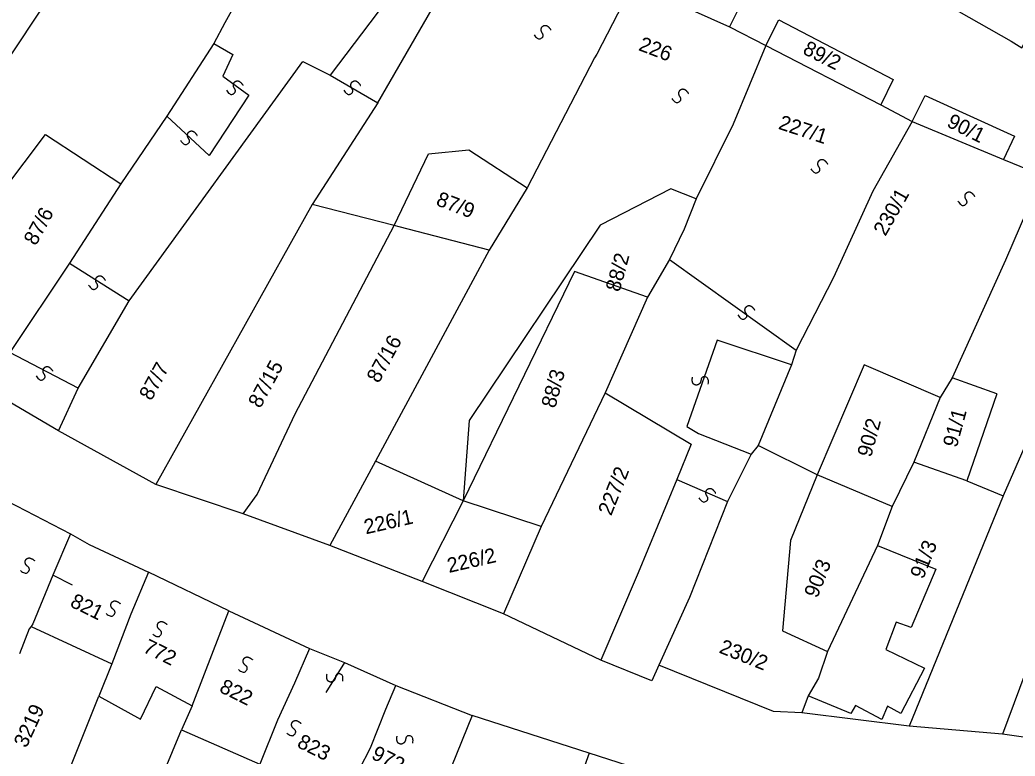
# Model space of a CAD drawing. Extents: x -581999 to -572728, y -1219553 to -1212032.
# Drawn here: x -578208.2 to -578073.6, y -1215897.1 to -1215797.5 of the extents above; entities that cross this region are included whole.
import ezdxf

# ---------------------------------------------------------------- set-up
doc = ezdxf.new("R2010")
doc.units = 0
for name, color, linetype in [('Vrstva 1', 7, 'Continuous'), ('Vrstva 2', 7, 'Continuous'), ('Vrstva 4', 7, 'Continuous'), ('Vrstva 6', 7, 'Continuous')]:
    doc.layers.add(name, color=color, linetype=linetype)

msp = doc.modelspace()

# ---------------------------------------------------------------- linework, layer by layer
at = {"layer": 'Vrstva 1'}
for p, q in [((-578133.148, -1215831.536), (-578148.235, -1215862.576)), ((-578123.291, -1215835.015), (-578133.148, -1215831.536)), ((-578119.321, -1215859.694), (-578124.539, -1215872.309)), ((-578080.096, -1215859.877), (-578075.208, -1215861.874)), ((-578148.235, -1215862.576), (-578153.775, -1215873.463))]:
    msp.add_line(p, q, dxfattribs=at)
for points in [[(-578170.788, -1215780.545), (-578180.468, -1215797.94)], [(-578231.766, -1215836.027), (-578201.443, -1215790.286)], [(-578155.491, -1215790.809), (-578166.223, -1215805.007)], [(-578159.75, -1215808.746), (-578150.734, -1215793.081)], [(-578125.238, -1215792.614), (-578130.145, -1215802.172), (-578130.44, -1215802.654)], [(-578125.238, -1215792.614), (-578112.187, -1215798.456)], [(-578084.212, -1215794.651), (-578074.129, -1215800.41)], [(-578180.468, -1215797.94), (-578181.927, -1215800.729)], [(-578112.187, -1215798.456), (-578107.285, -1215800.983)], [(-578107.285, -1215800.983), (-578105.521, -1215797.542), (-578090.077, -1215805.59), (-578091.75, -1215809.03)], [(-578181.927, -1215800.729), (-578188.289, -1215810.551)], [(-578107.285, -1215800.983), (-578111.689, -1215811.643)], [(-578107.285, -1215800.983), (-578091.75, -1215809.03)], [(-578074.129, -1215800.41), (-578072.652, -1215801.296), (-578072.037, -1215800.152)], [(-578130.44, -1215802.654), (-578139.56, -1215820.226)], [(-578193.376, -1215835.515), (-578169.922, -1215803.135), (-578166.223, -1215805.007)], [(-578087.497, -1215811.275), (-578085.731, -1215807.742), (-578073.664, -1215813.244), (-578075.152, -1215816.405)], [(-578159.75, -1215808.746), (-578168.628, -1215822.506)], [(-578091.75, -1215809.03), (-578087.497, -1215811.275)], [(-578188.289, -1215810.551), (-578194.518, -1215819.709)], [(-578111.689, -1215811.643), (-578116.729, -1215821.731)], [(-578087.497, -1215811.275), (-578092.824, -1215820.696)], [(-578087.497, -1215811.275), (-578075.152, -1215816.405)], [(-578225.23, -1215840.186), (-578204.682, -1215813.018), (-578194.518, -1215819.709)], [(-578157.527, -1215825.326), (-578152.885, -1215815.634), (-578147.463, -1215815.116), (-578139.56, -1215820.226)], [(-578075.152, -1215816.405), (-578071.73, -1215817.81)], [(-578070.039, -1215818.857), (-578074.879, -1215830.017), (-578082.113, -1215845.93)], [(-578194.518, -1215819.709), (-578201.475, -1215830.426)], [(-578139.56, -1215820.226), (-578144.709, -1215828.681)], [(-578116.729, -1215821.731), (-578120.146, -1215820.387), (-578129.671, -1215825.28), (-578147.425, -1215851.682), (-578148.235, -1215862.576)], [(-578092.824, -1215820.696), (-578098.132, -1215832.377)], [(-578168.628, -1215822.506), (-578189.798, -1215860.374)], [(-578157.527, -1215825.326), (-578168.628, -1215822.506)], [(-578116.729, -1215821.731), (-578118.322, -1215825.846)], [(-578176.09, -1215861.696), (-578170.918, -1215850.812), (-578157.527, -1215825.326)], [(-578156.88, -1215825.496), (-578157.527, -1215825.326)], [(-578144.709, -1215828.681), (-578156.88, -1215825.496)], [(-578118.322, -1215825.846), (-578120.326, -1215829.93)], [(-578144.709, -1215828.681), (-578160.088, -1215857.216)], [(-578201.475, -1215830.426), (-578209.516, -1215842.511)], [(-578120.326, -1215829.93), (-578123.291, -1215835.015), (-578128.997, -1215847.974)], [(-578098.132, -1215832.377), (-578103.171, -1215842.196)], [(-578200.268, -1215847.328), (-578193.376, -1215835.515)], [(-578103.171, -1215842.196), (-578103.835, -1215844.188)], [(-578103.835, -1215844.188), (-578108.347, -1215855.071)], [(-578083.703, -1215848.582), (-578093.998, -1215844.174), (-578100.367, -1215859.037)], [(-578082.113, -1215845.93), (-578083.703, -1215848.582)], [(-578076.059, -1215848.085), (-578082.113, -1215845.93)], [(-578202.918, -1215853.089), (-578212.731, -1215847.387)], [(-578202.918, -1215853.089), (-578200.268, -1215847.328)], [(-578128.997, -1215847.974), (-578137.667, -1215866.016)], [(-578128.997, -1215847.974), (-578117.397, -1215854.916)], [(-578076.059, -1215848.085), (-578080.096, -1215859.877), (-578087.286, -1215857.341)], [(-578083.703, -1215848.582), (-578087.286, -1215857.341)], [(-578070.393, -1215850.865), (-578075.208, -1215861.874), (-578087.892, -1215893.03)], [(-578189.798, -1215860.374), (-578202.918, -1215853.089)], [(-578117.397, -1215854.916), (-578119.321, -1215859.694)], [(-578108.347, -1215855.071), (-578109.274, -1215856.264)], [(-578100.367, -1215859.037), (-578108.347, -1215855.071)], [(-578109.274, -1215856.264), (-578112.455, -1215862.633)], [(-578160.088, -1215857.216), (-578166.258, -1215868.595)], [(-578148.235, -1215862.576), (-578160.088, -1215857.216)], [(-578087.286, -1215857.341), (-578090.203, -1215863.312)], [(-578100.367, -1215859.037), (-578103.951, -1215867.929), (-578105.03, -1215880.146)], [(-578090.203, -1215863.312), (-578100.367, -1215859.037)], [(-578177.949, -1215864.311), (-578189.798, -1215860.374)], [(-578212.307, -1215861.346), (-578201.33, -1215867.035)], [(-578177.949, -1215864.311), (-578176.09, -1215861.696)], [(-578062.948, -1215860.927), (-578075.305, -1215894.097)], [(-578137.667, -1215866.016), (-578148.235, -1215862.576)], [(-578112.455, -1215862.633), (-578117.631, -1215875.639)], [(-578166.258, -1215868.595), (-578177.949, -1215864.311)], [(-578090.203, -1215863.312), (-578092.195, -1215868.62)], [(-578201.33, -1215867.035), (-578203.725, -1215872.596)], [(-578201.33, -1215867.035), (-578198.775, -1215868.468)], [(-578137.667, -1215866.016), (-578142.757, -1215877.861)], [(-578198.775, -1215868.468), (-578190.751, -1215872.223)], [(-578142.757, -1215877.861), (-578153.775, -1215873.463), (-578166.258, -1215868.595)], [(-578092.195, -1215868.62), (-578098.959, -1215882.948)], [(-578203.725, -1215872.596), (-578206.401, -1215879.215), (-578206.643, -1215879.549)], [(-578190.751, -1215872.223), (-578193.147, -1215877.88)], [(-578179.893, -1215877.421), (-578190.751, -1215872.223)], [(-578124.539, -1215872.309), (-578129.623, -1215884.124)], [(-578117.631, -1215875.639), (-578121.758, -1215884.793)], [(-578193.147, -1215877.88), (-578195.734, -1215884.593)], [(-578182.001, -1215882.791), (-578179.893, -1215877.421)], [(-578179.893, -1215877.421), (-578169.017, -1215882.531)], [(-578129.623, -1215884.124), (-578142.757, -1215877.861)], [(-578206.643, -1215879.549), (-578206.886, -1215879.884), (-578208.228, -1215883.24)], [(-578206.643, -1215879.549), (-578195.734, -1215884.593)], [(-578105.03, -1215880.146), (-578098.959, -1215882.948)], [(-578184.877, -1215890.269), (-578182.001, -1215882.791)], [(-578169.017, -1215882.531), (-578171.028, -1215887.229)], [(-578169.017, -1215882.531), (-578164.261, -1215884.44), (-578157.303, -1215887.545)], [(-578098.959, -1215882.948), (-578100.154, -1215886.532)], [(-578195.734, -1215884.593), (-578197.478, -1215888.994)], [(-578121.758, -1215884.793), (-578122.685, -1215886.893), (-578129.623, -1215884.124)], [(-578102.414, -1215891.231), (-578106.242, -1215891.051), (-578121.758, -1215884.793)], [(-578171.028, -1215887.229), (-578173.327, -1215892.214)], [(-578100.154, -1215886.532), (-578101.553, -1215888.916), (-578102.414, -1215891.231)], [(-578197.478, -1215888.994), (-578191.849, -1215892.077), (-578189.742, -1215887.668), (-578184.877, -1215890.269)], [(-578160.752, -1215895.963), (-578158.694, -1215890.757), (-578157.303, -1215887.545)], [(-578157.303, -1215887.545), (-578147.001, -1215891.58)], [(-578203.706, -1215904.526), (-578197.478, -1215888.994)], [(-578184.877, -1215890.269), (-578186.313, -1215893.529)], [(-578087.892, -1215893.03), (-578102.414, -1215891.231)], [(-578173.327, -1215892.214), (-578175.722, -1215898.158)], [(-578147.001, -1215891.58), (-578149.78, -1215898.481)], [(-578131.187, -1215896.691), (-578147.001, -1215891.58)], [(-578193.402, -1215910.593), (-578186.313, -1215893.529)], [(-578186.313, -1215893.529), (-578175.722, -1215898.158)], [(-578075.305, -1215894.097), (-578087.892, -1215893.03)], [(-578063.912, -1215895.722), (-578075.305, -1215894.097)], [(-578164.775, -1215905.26), (-578162.221, -1215898.842), (-578160.752, -1215895.963)], [(-578131.187, -1215896.691), (-578133.775, -1215903.976)], [(-578120.696, -1215900.07), (-578131.187, -1215896.691)]]:
    msp.add_lwpolyline(points, dxfattribs=at)
at = {"layer": 'Vrstva 4'}
for p, q in [((-578092.195, -1215868.62), (-578084.314, -1215871.789)), ((-578084.314, -1215871.789), (-578087.634, -1215879.694)), ((-578089.677, -1215878.975), (-578091.082, -1215882.688)), ((-578087.634, -1215879.694), (-578089.677, -1215878.975)), ((-578091.082, -1215882.688), (-578085.846, -1215885.203)), ((-578085.846, -1215885.203), (-578089.039, -1215891.312)), ((-578095.806, -1215891.312), (-578101.553, -1215888.916)), ((-578095.168, -1215890.234), (-578095.806, -1215891.312)), ((-578091.593, -1215892.15), (-578095.168, -1215890.234)), ((-578090.826, -1215890.353), (-578091.593, -1215892.15)), ((-578089.039, -1215891.312), (-578090.826, -1215890.353))]:
    msp.add_line(p, q, dxfattribs=at)
for points in [[(-578123.711, -1215789.132), (-578110.701, -1215795.48), (-578112.187, -1215798.456)], [(-578181.927, -1215800.729), (-578179.384, -1215802.195), (-578180.726, -1215805.127), (-578177.203, -1215807.704), (-578182.565, -1215815.884), (-578188.289, -1215810.551)], [(-578166.223, -1215805.007), (-578159.75, -1215808.746)], [(-578201.475, -1215830.426), (-578193.376, -1215835.515)], [(-578120.326, -1215829.93), (-578103.171, -1215842.196)], [(-578103.835, -1215844.188), (-578113.871, -1215840.842), (-578117.987, -1215852.523), (-578116.404, -1215853.457)], [(-578200.268, -1215847.328), (-578209.516, -1215842.511)], [(-578116.404, -1215853.457), (-578109.274, -1215856.264)], [(-578119.321, -1215859.694), (-578112.455, -1215862.633)], [(-578201.069, -1215873.973), (-578203.725, -1215872.596)], [(-578164.261, -1215884.44), (-578166.78, -1215888.483)]]:
    msp.add_lwpolyline(points, dxfattribs=at)
at = {"layer": 'Vrstva 6'}
for points in [[(-578138.625, -1215799.532), (-578138.145, -1215800.239), (-578137.451, -1215799.928), (-578137.374, -1215799.528), (-578137.61, -1215799.183), (-578137.695, -1215798.851), (-578137.613, -1215798.561), (-578137.469, -1215798.381), (-578137.233, -1215798.253), (-578136.868, -1215798.289), (-578136.441, -1215798.728), (-578136.386, -1215798.901)], [(-578180.243, -1215807.038), (-578179.763, -1215807.745), (-578179.069, -1215807.434), (-578178.992, -1215807.034), (-578179.228, -1215806.689), (-578179.313, -1215806.357), (-578179.231, -1215806.067), (-578179.087, -1215805.887), (-578178.851, -1215805.759), (-578178.486, -1215805.795), (-578178.059, -1215806.234), (-578178.004, -1215806.407)], [(-578164.363, -1215807.039), (-578163.883, -1215807.746), (-578163.189, -1215807.435), (-578163.112, -1215807.035), (-578163.348, -1215806.69), (-578163.433, -1215806.358), (-578163.351, -1215806.068), (-578163.207, -1215805.888), (-578162.971, -1215805.76), (-578162.606, -1215805.796), (-578162.179, -1215806.235), (-578162.124, -1215806.408)], [(-578120.006, -1215808.137), (-578119.526, -1215808.844), (-578118.832, -1215808.533), (-578118.755, -1215808.133), (-578118.991, -1215807.788), (-578119.076, -1215807.456), (-578118.994, -1215807.166), (-578118.85, -1215806.986), (-578118.614, -1215806.858), (-578118.249, -1215806.894), (-578117.822, -1215807.333), (-578117.767, -1215807.506)], [(-578186.449, -1215813.812), (-578185.969, -1215814.519), (-578185.275, -1215814.208), (-578185.198, -1215813.808), (-578185.434, -1215813.463), (-578185.519, -1215813.131), (-578185.437, -1215812.841), (-578185.293, -1215812.661), (-578185.057, -1215812.533), (-578184.692, -1215812.569), (-578184.265, -1215813.008), (-578184.21, -1215813.181)], [(-578101.204, -1215817.658), (-578100.724, -1215818.365), (-578100.03, -1215818.054), (-578099.953, -1215817.654), (-578100.189, -1215817.309), (-578100.274, -1215816.977), (-578100.192, -1215816.687), (-578100.048, -1215816.507), (-578099.812, -1215816.379), (-578099.447, -1215816.415), (-578099.02, -1215816.854), (-578098.965, -1215817.027)], [(-578081.307, -1215822.052), (-578080.827, -1215822.759), (-578080.133, -1215822.448), (-578080.056, -1215822.048), (-578080.292, -1215821.703), (-578080.377, -1215821.371), (-578080.295, -1215821.081), (-578080.151, -1215820.901), (-578079.915, -1215820.773), (-578079.55, -1215820.809), (-578079.123, -1215821.248), (-578079.068, -1215821.421)], [(-578198.862, -1215833.402), (-578198.382, -1215834.109), (-578197.688, -1215833.798), (-578197.611, -1215833.398), (-578197.847, -1215833.053), (-578197.932, -1215832.721), (-578197.85, -1215832.431), (-578197.706, -1215832.251), (-578197.47, -1215832.123), (-578197.105, -1215832.159), (-578196.678, -1215832.598), (-578196.623, -1215832.771)], [(-578111.061, -1215837.431), (-578110.581, -1215838.138), (-578109.887, -1215837.827), (-578109.81, -1215837.427), (-578110.046, -1215837.082), (-578110.131, -1215836.75), (-578110.049, -1215836.46), (-578109.905, -1215836.28), (-578109.669, -1215836.152), (-578109.304, -1215836.188), (-578108.877, -1215836.627), (-578108.822, -1215836.8)], [(-578205.981, -1215845.67), (-578205.501, -1215846.377), (-578204.807, -1215846.066), (-578204.73, -1215845.666), (-578204.966, -1215845.321), (-578205.051, -1215844.989), (-578204.969, -1215844.699), (-578204.825, -1215844.519), (-578204.589, -1215844.391), (-578204.224, -1215844.427), (-578203.797, -1215844.866), (-578203.742, -1215845.039)], [(-578115.074, -1215846.797), (-578114.979, -1215845.946), (-578115.709, -1215845.734), (-578116.026, -1215845.988), (-578116.071, -1215846.404), (-578116.222, -1215846.711), (-578116.471, -1215846.878), (-578116.698, -1215846.922), (-578116.961, -1215846.866), (-578117.216, -1215846.602), (-578117.256, -1215845.992), (-578117.186, -1215845.823)], [(-578116.355, -1215862.147), (-578115.875, -1215862.854), (-578115.181, -1215862.543), (-578115.104, -1215862.143), (-578115.34, -1215861.798), (-578115.425, -1215861.466), (-578115.343, -1215861.176), (-578115.199, -1215860.996), (-578114.963, -1215860.868), (-578114.598, -1215860.904), (-578114.171, -1215861.343), (-578114.116, -1215861.516)], [(-578208.091, -1215872.002), (-578207.408, -1215872.515), (-578206.852, -1215871.995), (-578206.91, -1215871.592), (-578207.246, -1215871.342), (-578207.433, -1215871.056), (-578207.45, -1215870.755), (-578207.373, -1215870.538), (-578207.191, -1215870.341), (-578206.834, -1215870.256), (-578206.288, -1215870.532), (-578206.179, -1215870.678)], [(-578196.504, -1215877.813), (-578195.821, -1215878.326), (-578195.265, -1215877.806), (-578195.323, -1215877.403), (-578195.659, -1215877.153), (-578195.846, -1215876.867), (-578195.863, -1215876.566), (-578195.786, -1215876.349), (-578195.604, -1215876.152), (-578195.247, -1215876.067), (-578194.701, -1215876.343), (-578194.592, -1215876.489)], [(-578190.206, -1215880.593), (-578189.523, -1215881.106), (-578188.967, -1215880.586), (-578189.025, -1215880.183), (-578189.361, -1215879.933), (-578189.548, -1215879.647), (-578189.565, -1215879.346), (-578189.488, -1215879.129), (-578189.306, -1215878.932), (-578188.949, -1215878.847), (-578188.403, -1215879.123), (-578188.294, -1215879.269)], [(-578178.618, -1215885.393), (-578177.935, -1215885.906), (-578177.379, -1215885.386), (-578177.437, -1215884.983), (-578177.773, -1215884.733), (-578177.96, -1215884.447), (-578177.977, -1215884.146), (-578177.9, -1215883.929), (-578177.718, -1215883.732), (-578177.361, -1215883.647), (-578176.815, -1215883.923), (-578176.706, -1215884.069)], [(-578164.504, -1215886.957), (-578164.409, -1215886.106), (-578165.139, -1215885.894), (-578165.456, -1215886.148), (-578165.501, -1215886.564), (-578165.652, -1215886.871), (-578165.901, -1215887.038), (-578166.128, -1215887.082), (-578166.391, -1215887.026), (-578166.646, -1215886.762), (-578166.686, -1215886.152), (-578166.616, -1215885.983)], [(-578172.069, -1215893.984), (-578171.386, -1215894.497), (-578170.83, -1215893.977), (-578170.888, -1215893.574), (-578171.224, -1215893.324), (-578171.411, -1215893.038), (-578171.428, -1215892.737), (-578171.351, -1215892.52), (-578171.169, -1215892.323), (-578170.812, -1215892.238), (-578170.266, -1215892.514), (-578170.157, -1215892.66)], [(-578155.017, -1215895.343), (-578154.922, -1215894.492), (-578155.652, -1215894.28), (-578155.969, -1215894.534), (-578156.014, -1215894.95), (-578156.165, -1215895.257), (-578156.414, -1215895.424), (-578156.641, -1215895.468), (-578156.904, -1215895.412), (-578157.159, -1215895.148), (-578157.199, -1215894.538), (-578157.129, -1215894.369)]]:
    msp.add_open_spline(points, degree=2, dxfattribs=at)

# ---------------------------------------------------------------- texts
at = {"layer": 'Vrstva 2'}
for s, rotation, p in [('226', 339.1344, (-578124.629, -1215801.591)), ('89/2', 333.12485, (-578102.43, -1215802.033)), ('227/1', 341.69735, (-578105.707, -1215812.237)), ('90/1', 333.12485, (-578082.946, -1215811.886)), ('87/9', 339.1344, (-578152.012, -1215822.547)), ('230/1', 60.40476, (-578091.129, -1215826.877)), ('87/6', 61.55612, (-578206.006, -1215828.161)), ('88/2', 74.82418, (-578127.068, -1215834.41)), ('87/16', 61.55612, (-578159.633, -1215846.763)), ('87/7', 61.55612, (-578190.397, -1215849.131)), ('87/15', 61.55612, (-578175.657, -1215850.162)), ('88/3', 74.82418, (-578135.776, -1215850.135)), ('91/1', 74.82418, (-578081.469, -1215855.453)), ('90/2', 74.82418, (-578093.052, -1215856.765)), ('227/2', 68.28267, (-578128.202, -1215864.679)), ('226/1', 12.93748, (-578161.377, -1215867.102)), ('91/3', 68.28267, (-578086.004, -1215873.245)), ('226/2', 12.93748, (-578150.135, -1215872.323)), ('90/3', 68.28267, (-578100.336, -1215875.816)), ('821', 333.68301, (-578201.512, -1215876.784)), ('772', 333.68301, (-578191.645, -1215882.943)), ('230/2', 338.19127, (-578113.737, -1215883.061)), ('822', 333.68301, (-578181.324, -1215888.341)), ('3219', 65.27093, (-578207.278, -1215896.081)), ('823', 333.68301, (-578170.813, -1215895.796)), ('972', 333.68301, (-578160.758, -1215897.371))]:
    msp.add_text(s, height=2, rotation=rotation, dxfattribs=at).set_placement(p)

doc.saveas('drawing.dxf')
